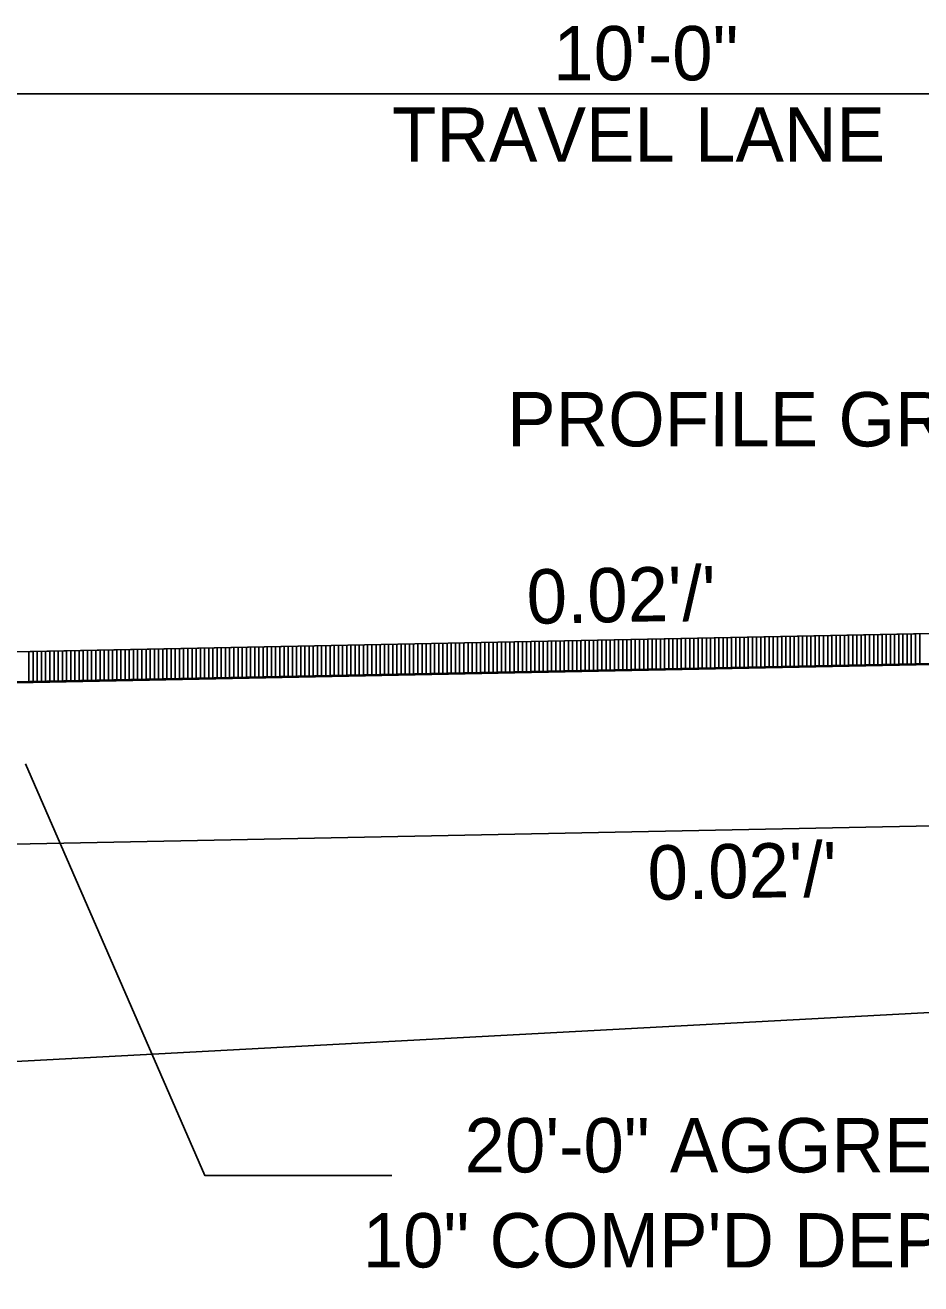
# Model space of a CAD drawing. Extents: x 1373719 to 1374161, y 379835 to 380167.
# Drawn here: x 1373950.36 to 1373961.07, y 379968.75 to 379983.81 of the extents above; entities that cross this region are included whole.
import ezdxf

# ---------------------------------------------------------------- set-up
doc = ezdxf.new("R2010")
doc.units = 0
for name, color, linetype in [('ACHM Surface', 7, 'Continuous'), ('Agg Base Course Text', 7, 'Continuous'), ('GREEN_TXT', 7, 'Continuous'), ('Pavement Layers', 7, 'Continuous'), ('SIGNATURE', 7, 'Continuous'), ('T_Drafting', 7, 'Continuous')]:
    doc.layers.add(name, color=color, linetype=linetype)

msp = doc.modelspace()

# ---------------------------------------------------------------- linework, layer by layer
for p, q in [((1373965.355, 379976.619), (1373948.855, 379976.289)), ((1373965.355, 379974.318), (1373938.705, 379973.785))]:
    msp.add_line(p, q)
at = {"layer": 'ACHM Surface'}
for p, q in [((1373959.106, 379976.124), (1373959.106, 379976.494)), ((1373959.156, 379976.125), (1373959.156, 379976.495)), ((1373959.206, 379976.126), (1373959.206, 379976.496)), ((1373959.256, 379976.127), (1373959.256, 379976.497)), ((1373959.306, 379976.128), (1373959.306, 379976.498)), ((1373959.356, 379976.129), (1373959.356, 379976.499)), ((1373959.406, 379976.13), (1373959.406, 379976.5)), ((1373959.456, 379976.131), (1373959.456, 379976.501)), ((1373959.506, 379976.132), (1373959.506, 379976.502)), ((1373959.556, 379976.133), (1373959.556, 379976.503)), ((1373959.606, 379976.134), (1373959.606, 379976.504)), ((1373959.656, 379976.135), (1373959.656, 379976.505)), ((1373959.706, 379976.136), (1373959.706, 379976.506)), ((1373959.756, 379976.137), (1373959.756, 379976.507)), ((1373959.806, 379976.138), (1373959.806, 379976.508)), ((1373959.856, 379976.139), (1373959.856, 379976.509)), ((1373959.906, 379976.14), (1373959.906, 379976.51)), ((1373959.956, 379976.141), (1373959.956, 379976.511)), ((1373960.006, 379976.142), (1373960.006, 379976.512)), ((1373960.056, 379976.143), (1373960.056, 379976.513)), ((1373960.106, 379976.144), (1373960.106, 379976.514)), ((1373960.156, 379976.145), (1373960.156, 379976.515)), ((1373960.206, 379976.146), (1373960.206, 379976.516)), ((1373960.256, 379976.147), (1373960.256, 379976.517)), ((1373960.306, 379976.148), (1373960.306, 379976.518)), ((1373960.356, 379976.149), (1373960.356, 379976.519)), ((1373960.406, 379976.15), (1373960.406, 379976.52)), ((1373960.456, 379976.151), (1373960.456, 379976.521)), ((1373960.506, 379976.152), (1373960.506, 379976.522)), ((1373960.556, 379976.153), (1373960.556, 379976.523)), ((1373960.606, 379976.154), (1373960.606, 379976.524)), ((1373960.656, 379976.155), (1373960.656, 379976.525)), ((1373960.706, 379976.156), (1373960.706, 379976.526)), ((1373960.756, 379976.157), (1373960.756, 379976.527)), ((1373960.806, 379976.158), (1373960.806, 379976.528)), ((1373960.856, 379976.159), (1373960.856, 379976.529)), ((1373960.906, 379976.16), (1373960.906, 379976.53)), ((1373960.956, 379976.161), (1373960.956, 379976.531)), ((1373961.006, 379976.162), (1373961.006, 379976.532)), ((1373961.056, 379976.163), (1373961.056, 379976.533)), ((1373951.606, 379975.974), (1373951.606, 379976.344)), ((1373951.656, 379975.975), (1373951.656, 379976.345)), ((1373951.706, 379975.976), (1373951.706, 379976.346)), ((1373951.756, 379975.977), (1373951.756, 379976.347)), ((1373951.806, 379975.978), (1373951.806, 379976.348)), ((1373951.856, 379975.979), (1373951.856, 379976.349)), ((1373951.906, 379975.98), (1373951.906, 379976.35)), ((1373951.956, 379975.981), (1373951.956, 379976.351)), ((1373952.006, 379975.982), (1373952.006, 379976.352)), ((1373952.056, 379975.983), (1373952.056, 379976.353)), ((1373952.106, 379975.984), (1373952.106, 379976.354)), ((1373952.156, 379975.985), (1373952.156, 379976.355)), ((1373952.206, 379975.986), (1373952.206, 379976.356)), ((1373952.256, 379975.987), (1373952.256, 379976.357)), ((1373952.306, 379975.988), (1373952.306, 379976.358)), ((1373952.356, 379975.989), (1373952.356, 379976.359)), ((1373952.406, 379975.99), (1373952.406, 379976.36)), ((1373952.456, 379975.991), (1373952.456, 379976.361)), ((1373952.506, 379975.992), (1373952.506, 379976.362)), ((1373952.556, 379975.993), (1373952.556, 379976.363)), ((1373952.606, 379975.994), (1373952.606, 379976.364)), ((1373952.656, 379975.995), (1373952.656, 379976.365)), ((1373952.706, 379975.996), (1373952.706, 379976.366)), ((1373952.756, 379975.997), (1373952.756, 379976.367)), ((1373952.806, 379975.998), (1373952.806, 379976.368)), ((1373952.856, 379975.999), (1373952.856, 379976.369)), ((1373952.906, 379976), (1373952.906, 379976.37)), ((1373952.956, 379976.001), (1373952.956, 379976.371)), ((1373953.006, 379976.002), (1373953.006, 379976.372)), ((1373953.056, 379976.003), (1373953.056, 379976.373)), ((1373953.106, 379976.004), (1373953.106, 379976.374)), ((1373953.156, 379976.005), (1373953.156, 379976.375)), ((1373953.206, 379976.006), (1373953.206, 379976.376)), ((1373953.256, 379976.007), (1373953.256, 379976.377)), ((1373953.306, 379976.008), (1373953.306, 379976.378)), ((1373953.356, 379976.009), (1373953.356, 379976.379)), ((1373953.406, 379976.01), (1373953.406, 379976.38)), ((1373953.456, 379976.011), (1373953.456, 379976.381)), ((1373953.506, 379976.012), (1373953.506, 379976.382)), ((1373953.556, 379976.013), (1373953.556, 379976.383)), ((1373953.606, 379976.014), (1373953.606, 379976.384)), ((1373953.656, 379976.015), (1373953.656, 379976.385)), ((1373953.706, 379976.016), (1373953.706, 379976.386)), ((1373953.756, 379976.017), (1373953.756, 379976.387)), ((1373953.806, 379976.018), (1373953.806, 379976.388)), ((1373953.856, 379976.019), (1373953.856, 379976.389)), ((1373953.906, 379976.02), (1373953.906, 379976.39)), ((1373953.956, 379976.021), (1373953.956, 379976.391)), ((1373954.006, 379976.022), (1373954.006, 379976.392)), ((1373954.056, 379976.023), (1373954.056, 379976.393)), ((1373954.106, 379976.024), (1373954.106, 379976.394)), ((1373954.156, 379976.025), (1373954.156, 379976.395)), ((1373954.206, 379976.026), (1373954.206, 379976.396)), ((1373954.256, 379976.027), (1373954.256, 379976.397)), ((1373954.306, 379976.028), (1373954.306, 379976.398)), ((1373954.356, 379976.029), (1373954.356, 379976.399)), ((1373954.406, 379976.03), (1373954.406, 379976.4)), ((1373954.456, 379976.031), (1373954.456, 379976.401)), ((1373954.506, 379976.032), (1373954.506, 379976.402)), ((1373954.556, 379976.033), (1373954.556, 379976.403)), ((1373954.606, 379976.034), (1373954.606, 379976.404)), ((1373954.656, 379976.035), (1373954.656, 379976.405)), ((1373954.706, 379976.036), (1373954.706, 379976.406)), ((1373954.756, 379976.037), (1373954.756, 379976.407)), ((1373954.806, 379976.038), (1373954.806, 379976.408)), ((1373954.856, 379976.039), (1373954.856, 379976.409)), ((1373954.906, 379976.04), (1373954.906, 379976.41)), ((1373954.956, 379976.041), (1373954.956, 379976.411)), ((1373955.006, 379976.042), (1373955.006, 379976.412)), ((1373955.056, 379976.043), (1373955.056, 379976.413)), ((1373955.106, 379976.044), (1373955.106, 379976.414)), ((1373955.156, 379976.045), (1373955.156, 379976.415)), ((1373955.206, 379976.046), (1373955.206, 379976.416)), ((1373955.256, 379976.047), (1373955.256, 379976.417)), ((1373955.306, 379976.048), (1373955.306, 379976.418)), ((1373955.356, 379976.049), (1373955.356, 379976.419)), ((1373955.406, 379976.05), (1373955.406, 379976.42)), ((1373955.456, 379976.051), (1373955.456, 379976.421)), ((1373955.506, 379976.052), (1373955.506, 379976.422)), ((1373955.556, 379976.053), (1373955.556, 379976.423)), ((1373955.606, 379976.054), (1373955.606, 379976.424)), ((1373955.656, 379976.055), (1373955.656, 379976.425)), ((1373955.706, 379976.056), (1373955.706, 379976.426)), ((1373955.756, 379976.057), (1373955.756, 379976.427)), ((1373955.806, 379976.058), (1373955.806, 379976.428)), ((1373955.856, 379976.059), (1373955.856, 379976.429)), ((1373955.906, 379976.06), (1373955.906, 379976.43)), ((1373955.956, 379976.061), (1373955.956, 379976.431)), ((1373956.006, 379976.062), (1373956.006, 379976.432)), ((1373956.056, 379976.063), (1373956.056, 379976.433)), ((1373956.106, 379976.064), (1373956.106, 379976.434)), ((1373956.156, 379976.065), (1373956.156, 379976.435)), ((1373956.206, 379976.066), (1373956.206, 379976.436)), ((1373956.256, 379976.067), (1373956.256, 379976.437)), ((1373956.306, 379976.068), (1373956.306, 379976.438)), ((1373956.356, 379976.069), (1373956.356, 379976.439)), ((1373956.406, 379976.07), (1373956.406, 379976.44)), ((1373956.456, 379976.071), (1373956.456, 379976.441)), ((1373956.506, 379976.072), (1373956.506, 379976.442)), ((1373956.556, 379976.073), (1373956.556, 379976.443)), ((1373956.606, 379976.074), (1373956.606, 379976.444)), ((1373956.656, 379976.075), (1373956.656, 379976.445)), ((1373956.706, 379976.076), (1373956.706, 379976.446)), ((1373956.756, 379976.077), (1373956.756, 379976.447)), ((1373956.806, 379976.078), (1373956.806, 379976.448)), ((1373956.856, 379976.079), (1373956.856, 379976.449)), ((1373956.906, 379976.08), (1373956.906, 379976.45)), ((1373956.956, 379976.081), (1373956.956, 379976.451)), ((1373957.006, 379976.082), (1373957.006, 379976.452)), ((1373957.056, 379976.083), (1373957.056, 379976.453)), ((1373957.106, 379976.084), (1373957.106, 379976.454)), ((1373957.156, 379976.085), (1373957.156, 379976.455)), ((1373957.206, 379976.086), (1373957.206, 379976.456)), ((1373957.256, 379976.087), (1373957.256, 379976.457)), ((1373957.306, 379976.088), (1373957.306, 379976.458)), ((1373957.356, 379976.089), (1373957.356, 379976.459)), ((1373957.406, 379976.09), (1373957.406, 379976.46)), ((1373957.456, 379976.091), (1373957.456, 379976.461)), ((1373957.506, 379976.092), (1373957.506, 379976.462)), ((1373957.556, 379976.093), (1373957.556, 379976.463)), ((1373957.606, 379976.094), (1373957.606, 379976.464)), ((1373957.656, 379976.095), (1373957.656, 379976.465)), ((1373957.706, 379976.096), (1373957.706, 379976.466)), ((1373957.756, 379976.097), (1373957.756, 379976.467)), ((1373957.806, 379976.098), (1373957.806, 379976.468)), ((1373957.856, 379976.099), (1373957.856, 379976.469)), ((1373957.906, 379976.1), (1373957.906, 379976.47)), ((1373957.956, 379976.101), (1373957.956, 379976.471)), ((1373958.006, 379976.102), (1373958.006, 379976.472)), ((1373958.056, 379976.103), (1373958.056, 379976.473)), ((1373958.106, 379976.104), (1373958.106, 379976.474)), ((1373958.156, 379976.105), (1373958.156, 379976.475)), ((1373958.206, 379976.106), (1373958.206, 379976.476)), ((1373958.256, 379976.107), (1373958.256, 379976.477)), ((1373958.306, 379976.108), (1373958.306, 379976.478)), ((1373958.356, 379976.109), (1373958.356, 379976.479)), ((1373958.406, 379976.11), (1373958.406, 379976.48)), ((1373958.456, 379976.111), (1373958.456, 379976.481)), ((1373958.506, 379976.112), (1373958.506, 379976.482)), ((1373958.556, 379976.113), (1373958.556, 379976.483)), ((1373958.606, 379976.114), (1373958.606, 379976.484)), ((1373958.656, 379976.115), (1373958.656, 379976.485)), ((1373958.706, 379976.116), (1373958.706, 379976.486)), ((1373958.756, 379976.117), (1373958.756, 379976.487)), ((1373958.806, 379976.118), (1373958.806, 379976.488)), ((1373958.856, 379976.119), (1373958.856, 379976.489)), ((1373958.906, 379976.12), (1373958.906, 379976.49)), ((1373958.956, 379976.121), (1373958.956, 379976.491)), ((1373959.006, 379976.122), (1373959.006, 379976.492)), ((1373959.056, 379976.123), (1373959.056, 379976.493)), ((1373950.406, 379975.95), (1373950.406, 379976.32)), ((1373950.456, 379975.951), (1373950.456, 379976.321)), ((1373950.506, 379975.952), (1373950.506, 379976.322)), ((1373950.556, 379975.953), (1373950.556, 379976.323)), ((1373950.606, 379975.954), (1373950.606, 379976.324)), ((1373950.656, 379975.955), (1373950.656, 379976.325)), ((1373950.706, 379975.956), (1373950.706, 379976.326)), ((1373950.756, 379975.957), (1373950.756, 379976.327)), ((1373950.806, 379975.958), (1373950.806, 379976.328)), ((1373950.856, 379975.959), (1373950.856, 379976.329)), ((1373950.906, 379975.96), (1373950.906, 379976.33)), ((1373950.956, 379975.961), (1373950.956, 379976.331)), ((1373951.006, 379975.962), (1373951.006, 379976.332)), ((1373951.056, 379975.963), (1373951.056, 379976.333)), ((1373951.106, 379975.964), (1373951.106, 379976.334)), ((1373951.156, 379975.965), (1373951.156, 379976.335)), ((1373951.206, 379975.966), (1373951.206, 379976.336)), ((1373951.256, 379975.967), (1373951.256, 379976.337)), ((1373951.306, 379975.968), (1373951.306, 379976.338)), ((1373951.356, 379975.969), (1373951.356, 379976.339)), ((1373951.406, 379975.97), (1373951.406, 379976.34)), ((1373951.456, 379975.971), (1373951.456, 379976.341)), ((1373951.506, 379975.972), (1373951.506, 379976.342)), ((1373951.556, 379975.973), (1373951.556, 379976.343))]:
    msp.add_line(p, q, dxfattribs=at)
at = {"layer": 'Agg Base Course Text'}
msp.add_lwpolyline([(1373954.745, 379970.052), (1373952.508, 379970.052), (1373950.367, 379974.975)], dxfattribs=at)
at = {"layer": 'GREEN_TXT'}
msp.add_line((1373948.855, 379982.992), (1373965.355, 379982.992), dxfattribs=at)
at = {"layer": 'Pavement Layers'}
msp.add_line((1373965.355, 379976.249), (1373948.857, 379975.919), dxfattribs=at)
at = {"layer": 'SIGNATURE'}
msp.add_line((1373965.355, 379976.258), (1373948.86, 379975.928), dxfattribs=at)
msp.add_lwpolyline([(1373945.855, 379975.798), (1373946.24, 379976.184), (1373948.855, 379976.289), (1373965.355, 379976.619), (1373981.855, 379976.289), (1373984.469, 379976.184), (1373984.855, 379975.798), (1373981.847, 379975.919), (1373965.355, 379976.249), (1373948.862, 379975.919)], close=True, dxfattribs=at)
at = {"layer": 'T_Drafting'}
msp.add_lwpolyline([(1373907.347, 379968.924), (1373923.894, 379968.848), (1373942.81, 379971.015), (1373964.304, 379972.17), (1373992.078, 379975.291), (1374006.816, 379975.489), (1374019.984, 379975.489)], dxfattribs=at)

# ---------------------------------------------------------------- texts
at = {"layer": 'GREEN_TXT'}
for s, p in [('10\'-0"', (1373956.675, 379983.154)), ('TRAVEL LANE', (1373954.748, 379982.179)), ('20\'-0" AGGREGATE BASE CRSE. (CL. 7)', (1373955.614, 379970.087)), ('10" COMP\'D DEPTH (129.75 TONS PER STA.)', (1373954.396, 379968.95))]:
    msp.add_text(s, height=0.65, dxfattribs=at).set_placement(p)
for s, rotation, p in [('PROFILE GRADE', 359.98, (1373956.124, 379978.775)), ("0.02'/'", 1.1458, (1373956.363, 379976.65)), ("0.02'/'", 1.146, (1373957.809, 379973.347))]:
    msp.add_text(s, height=0.65, rotation=rotation, dxfattribs=at).set_placement(p)

doc.saveas('drawing.dxf')
